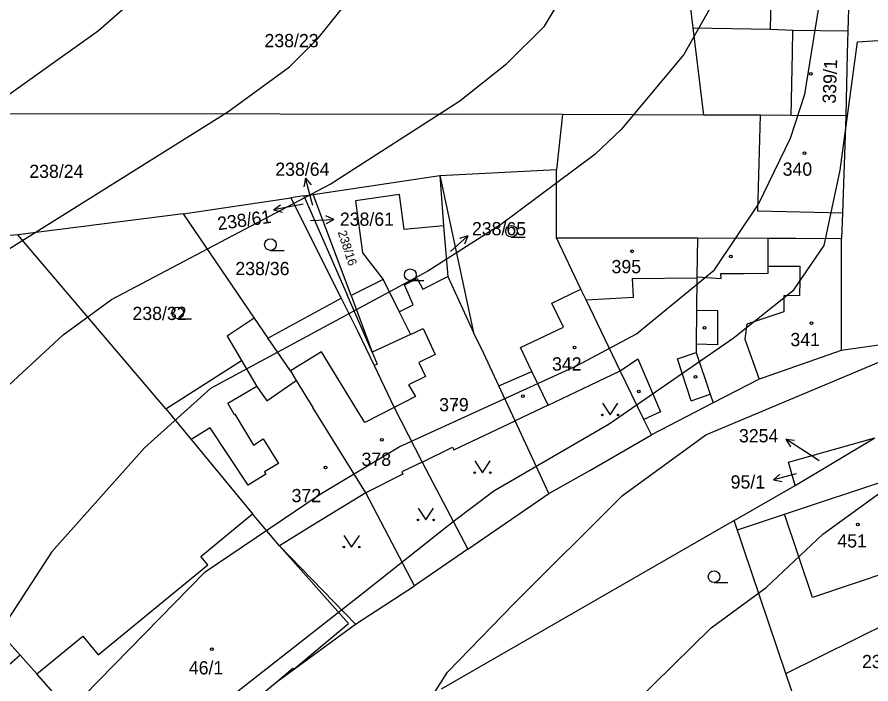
# Model space of a CAD drawing. Extents: x -555860 to -552701, y -1187050 to -1182291.
# Drawn here: x -554606.3 to -554496.6, y -1184422.8 to -1184337.1 of the extents above; entities that cross this region are included whole.
import ezdxf

# ---------------------------------------------------------------- set-up
doc = ezdxf.new("R2010")
doc.units = 0
for name, color, linetype in [('CYKLISTI_stav', 7, 'Continuous'), ('LEG_2b', 7, 'Continuous'), ('Level 16', 7, 'Continuous'), ('Level 25', 7, 'Continuous'), ('Level 40', 7, 'Continuous'), ('Level 41', 7, 'Continuous'), ('navrh_BV', 7, 'Continuous'), ('Poz předměty', 7, 'Continuous'), ('stav_BV', 7, 'Continuous')]:
    doc.layers.add(name, color=color, linetype=linetype)

msp = doc.modelspace()

# ---------------------------------------------------------------- linework, layer by layer
at = {"layer": 'CYKLISTI_stav'}
for p, q in [((-554509.47, -1184338.72), (-554509.23, -1184325.48)), ((-554506.67, -1184341.74), (-554506.62, -1184338.84)), ((-554506.81, -1184349.79), (-554506.67, -1184341.74)), ((-554511.12, -1184362.08), (-554510.76, -1184349.77)), ((-554500.2, -1184362.32), (-554511.12, -1184362.08)), ((-554509.77, -1184369.16), (-554509.77, -1184365.53)), ((-554509.77, -1184369.16), (-554505.69, -1184369.14)), ((-554509.77, -1184370.06), (-554509.77, -1184369.16)), ((-554505.69, -1184369.14), (-554505.69, -1184370.04)), ((-554559.25, -1184370.87), (-554557.18, -1184375.01)), ((-554527.21, -1184370.71), (-554518.94, -1184370.66)), ((-554527.08, -1184373.14), (-554527.21, -1184370.71)), ((-554518.94, -1184370.51), (-554515.83, -1184370.75)), ((-554515.84, -1184370.08), (-554512.85, -1184370.07)), ((-554515.83, -1184370.75), (-554515.84, -1184370.08)), ((-554512.85, -1184370.07), (-554509.77, -1184370.06)), ((-554505.69, -1184371.04), (-554505.76, -1184372.93)), ((-554505.69, -1184370.04), (-554505.69, -1184371.04)), ((-554537.59, -1184373.9), (-554533.83, -1184372.08)), ((-554533.16, -1184373.47), (-554527.08, -1184373.14)), ((-554507.75, -1184372.96), (-554507.76, -1184375.02)), ((-554505.76, -1184372.93), (-554507.75, -1184372.96)), ((-554536.09, -1184376.98), (-554537.59, -1184373.9)), ((-554557.18, -1184375.01), (-554555.72, -1184377.92)), ((-554518.98, -1184374.78), (-554516.29, -1184374.85)), ((-554516.29, -1184374.85), (-554516.3, -1184379.25)), ((-554507.76, -1184375.02), (-554512.5, -1184376.58)), ((-554512.5, -1184376.58), (-554512.77, -1184378.52)), ((-554555.72, -1184377.92), (-554554.09, -1184377.17)), ((-554554.09, -1184377.17), (-554552.57, -1184380.5)), ((-554541.58, -1184379.61), (-554536.09, -1184376.98)), ((-554555.72, -1184377.92), (-554560.66, -1184380.21)), ((-554512.77, -1184378.52), (-554510.93, -1184383.67)), ((-554540.12, -1184382.67), (-554541.58, -1184379.61)), ((-554516.3, -1184379.25), (-554519.02, -1184379.16)), ((-554567.17, -1184380.15), (-554571.16, -1184382.61)), ((-554562.22, -1184388.18), (-554567.17, -1184380.15)), ((-554552.57, -1184380.5), (-554554.65, -1184381.52)), ((-554521.44, -1184381.05), (-554519.03, -1184380.25)), ((-554577.44, -1184381.25), (-554575.45, -1184384.62)), ((-554554.65, -1184381.52), (-554553.8, -1184383.31)), ((-554528.8, -1184382.58), (-554526.51, -1184381.03)), ((-554526.51, -1184381.03), (-554523.62, -1184387.84)), ((-554519.65, -1184386.45), (-554521.44, -1184381.05)), ((-554544.38, -1184384.53), (-554540.12, -1184382.67)), ((-554538.05, -1184386.99), (-554540.12, -1184382.67)), ((-554574.17, -1184386.45), (-554570.42, -1184383.81)), ((-554553.8, -1184383.31), (-554556, -1184384.37)), ((-554575.45, -1184384.62), (-554579.19, -1184386.77)), ((-554575.45, -1184384.62), (-554574.17, -1184386.45)), ((-554556, -1184384.37), (-554555.07, -1184385.9)), ((-554555.07, -1184385.9), (-554557.83, -1184387.32)), ((-554519.65, -1184386.45), (-554517.22, -1184385.6)), ((-554579.19, -1184386.77), (-554578.37, -1184388.2)), ((-554557.83, -1184387.32), (-554561.58, -1184389.22)), ((-554538.05, -1184386.99), (-554542.3, -1184389)), ((-554578.37, -1184388.2), (-554578.28, -1184388.15)), ((-554578.28, -1184388.15), (-554575.91, -1184392.13)), ((-554561.58, -1184389.22), (-554562.22, -1184388.18)), ((-554523.62, -1184387.84), (-554525.73, -1184388.82)), ((-554581.45, -1184389.92), (-554583.89, -1184391.42)), ((-554576.56, -1184397.29), (-554581.45, -1184389.92)), ((-554575.91, -1184392.13), (-554574.67, -1184391.34)), ((-554574.67, -1184391.34), (-554572.69, -1184394.48)), ((-554572.69, -1184394.48), (-554574.48, -1184395.58)), ((-554554.23, -1184394.3), (-554556.84, -1184395.56)), ((-554574.3, -1184395.88), (-554576.56, -1184397.29)), ((-554574.48, -1184395.58), (-554574.3, -1184395.88)), ((-554556.69, -1184395.88), (-554561.48, -1184398.25)), ((-554556.84, -1184395.56), (-554556.69, -1184395.88)), ((-554507.68, -1184401.01), (-554492.26, -1184395.86)), ((-554561.48, -1184398.25), (-554568.25, -1184402.42)), ((-554504.1, -1184411.72), (-554507.68, -1184401.01)), ((-554568.25, -1184402.42), (-554572.55, -1184405.06)), ((-554563.7, -1184415.03), (-554572.55, -1184405.06)), ((-554488.71, -1184406.52), (-554504.1, -1184411.72)), ((-554570.73, -1184420.91), (-554563.7, -1184415.03)), ((-554605.87, -1184419.11), (-554608.01, -1184420.99)), ((-554572.85, -1184422.48), (-554570.82, -1184420.8)), ((-554570.82, -1184420.8), (-554570.73, -1184420.91))]:
    msp.add_line(p, q, dxfattribs=at)
for points in [[(-554557.18, -1184375.01), (-554555.38, -1184374.13), (-554556.5, -1184371.56), (-554554.88, -1184370.71), (-554554.14, -1184372.1), (-554550.93, -1184370.47)], [(-554538.05, -1184386.99), (-554532.63, -1184384.42), (-554528.8, -1184382.58)], [(-554554.23, -1184394.3), (-554550.31, -1184392.41), (-554550.16, -1184392.73), (-554542.3, -1184389)]]:
    msp.add_lwpolyline(points, dxfattribs=at)
at = {"layer": 'Level 16'}
for p, q in [((-554568.57, -1184363.3), (-554565.57, -1184363.15)), ((-554565.57, -1184363.15), (-554566.6, -1184362.7)), ((-554565.57, -1184363.15), (-554566.55, -1184363.7)), ((-554506.2, -1184395.81), (-554509.09, -1184396.6)), ((-554509.09, -1184396.6), (-554508.26, -1184395.86)), ((-554509.09, -1184396.6), (-554508, -1184396.82))]:
    msp.add_line(p, q, dxfattribs=at)
at = {"layer": 'Level 25'}
for p, q in [((-554542.76, -1184365.41), (-554541.01, -1184365.41)), ((-554573.72, -1184367.12), (-554571.97, -1184367.12)), ((-554555.75, -1184371), (-554554, -1184371)), ((-554585.62, -1184375.89), (-554583.87, -1184375.89)), ((-554516.73, -1184409.78), (-554514.98, -1184409.78))]:
    msp.add_line(p, q, dxfattribs=at)
for points in [[(-554531.07, -1184386.75), (-554530.07, -1184388.25), (-554529.07, -1184386.75)], [(-554547.47, -1184394.17), (-554546.47, -1184395.67), (-554545.47, -1184394.17)], [(-554554.75, -1184400.24), (-554553.75, -1184401.74), (-554552.75, -1184400.24)], [(-554564.29, -1184403.73), (-554563.29, -1184405.23), (-554562.29, -1184403.73)]]:
    msp.add_lwpolyline(points, dxfattribs=at)
for centre, radius in [((-554504.3, -1184344.45), 0.175), ((-554505.12, -1184354.64), 0.175), ((-554542.76, -1184364.66), 0.75), ((-554573.72, -1184366.37), 0.75), ((-554527.27, -1184367.24), 0.175), ((-554514.56, -1184367.91), 0.175), ((-554555.75, -1184370.25), 0.75), ((-554585.62, -1184375.14), 0.75), ((-554504.22, -1184376.47), 0.175), ((-554517.95, -1184377.05), 0.175), ((-554534.64, -1184379.6), 0.175), ((-554519.11, -1184383.36), 0.175), ((-554526.41, -1184385.24), 0.175), ((-554541.31, -1184385.84), 0.175), ((-554549.94, -1184386.96), 0.175), ((-554531.07, -1184388.25), 0.1), ((-554529.07, -1184388.25), 0.1), ((-554559.41, -1184391.46), 0.175), ((-554566.63, -1184395), 0.175), ((-554547.47, -1184395.67), 0.1), ((-554545.47, -1184395.67), 0.1), ((-554554.75, -1184401.74), 0.1), ((-554552.75, -1184401.74), 0.1), ((-554498.27, -1184402.34), 0.175), ((-554564.29, -1184405.23), 0.1), ((-554562.29, -1184405.23), 0.1), ((-554516.73, -1184409.03), 0.75), ((-554581.26, -1184418.35), 0.175)]:
    msp.add_circle(centre, radius, dxfattribs=at)
at = {"layer": 'Level 40'}
for points in [[(-554704.42, -1184410.9), (-554700.28, -1184411.43), (-554695.1, -1184411.42), (-554689.74, -1184411.01), (-554685.2, -1184410.27), (-554679.21, -1184408.38), (-554674.31, -1184406.3), (-554667.57, -1184402.23), (-554665.06, -1184399.12), (-554660.22, -1184394.29), (-554648.17, -1184387.43), (-554614.17, -1184371.18), (-554579.17, -1184349.31), (-554571.27, -1184343.52), (-554567.6, -1184339.86), (-554560.69, -1184331.25), (-554554.62, -1184321.09), (-554552.64, -1184316.01), (-554550.39, -1184305.85), (-554550.24, -1184300.77), (-554547.56, -1184285.53), (-554544.03, -1184275.37), (-554531.47, -1184246.3), (-554522.1, -1184219.47)], [(-554655.52, -1184508.62), (-554655.75, -1184500.69), (-554643.25, -1184493.97), (-554633.4, -1184486.78), (-554624.37, -1184479.93), (-554609.65, -1184462.12), (-554602.45, -1184466.42), (-554590.47, -1184463.78), (-554582.07, -1184460.56), (-554576.65, -1184457.21), (-554571.61, -1184452.75), (-554564.45, -1184442.43), (-554550.96, -1184421.3), (-554542.47, -1184412.5), (-554528.47, -1184398.59), (-554517.79, -1184390.83), (-554489.12, -1184378.8)]]:
    msp.add_lwpolyline(points, dxfattribs=at)
at = {"layer": 'Level 41'}
for points in [[(-554723.68, -1184371.89), (-554709.28, -1184375.13), (-554697.99, -1184376.55), (-554685.57, -1184375.98), (-554667.51, -1184373.72), (-554656.22, -1184371.32), (-554643.8, -1184367.23), (-554617.56, -1184353.69), (-554611.07, -1184349.73), (-554595.82, -1184338.87), (-554588.63, -1184332.52), (-554580.72, -1184323.77), (-554575.79, -1184315.73), (-554571.27, -1184305.85), (-554562.8, -1184278.47), (-554556.88, -1184263.94), (-554548.41, -1184246.86), (-554538.48, -1184222.06), (-554535, -1184209.25), (-554534.86, -1184191.85)], [(-554608.54, -1184385.49), (-554600.34, -1184377.96), (-554594.13, -1184373.44), (-554566.05, -1184358.62), (-554549.4, -1184347.9), (-554543.33, -1184343.1), (-554538.53, -1184338.3), (-554532.89, -1184328.99), (-554529.5, -1184318.55), (-554525.12, -1184288.35), (-554517.79, -1184265.77), (-554511.3, -1184251.94), (-554507.68, -1184243.65), (-554506.19, -1184238.79), (-554506.15, -1184230.44)], [(-554686.19, -1184509.5), (-554686.19, -1184504.67), (-554682.39, -1184501.42), (-554679.34, -1184497.68), (-554671.2, -1184491.48), (-554663.95, -1184488.11), (-554651.86, -1184482.13), (-554641.77, -1184475.91), (-554629.84, -1184466.75), (-554621.25, -1184458.3), (-554614.31, -1184450.12), (-554605.02, -1184434.45), (-554597.68, -1184424.32), (-554582.08, -1184408.39), (-554567.32, -1184398.42), (-554557.16, -1184392.35), (-554534.3, -1184381.91), (-554526.68, -1184377.82), (-554516.66, -1184369.63), (-554511.01, -1184361.16), (-554506.92, -1184352.7), (-554505.09, -1184347.05), (-554501.42, -1184324.48)], [(-554517.08, -1184335.76), (-554520.61, -1184341.97), (-554528.65, -1184351.57), (-554532.04, -1184354.81), (-554544.18, -1184363.84), (-554553.49, -1184369.77), (-554581.43, -1184384.87), (-554589.9, -1184392.49), (-554601.83, -1184405.89), (-554634, -1184455.39), (-554637.75, -1184460.66), (-554648.01, -1184471.89), (-554655.91, -1184478.12), (-554666.73, -1184484.09), (-554676.43, -1184487.97), (-554699.73, -1184495.18), (-554705.98, -1184496.32), (-554715.26, -1184497.4)], [(-554671.82, -1184510.68), (-554672.23, -1184504.37), (-554670.15, -1184502.15), (-554645.4, -1184485.96), (-554640.9, -1184483.53), (-554634.7, -1184478.1), (-554627.63, -1184472.97), (-554606.29, -1184450.17), (-554583.21, -1184427.88), (-554562.04, -1184411.29), (-554550.24, -1184401.95), (-554545.02, -1184398), (-554530.2, -1184389.39), (-554514.26, -1184378.38), (-554506.5, -1184372.17), (-554502.57, -1184366.47), (-554500.55, -1184356.83), (-554498.31, -1184340.33), (-554484.62, -1184339.43)], [(-554620.28, -1184511.96), (-554615.57, -1184502.26), (-554615.31, -1184496.89), (-554613.9, -1184495.46), (-554592.41, -1184483.26), (-554577.99, -1184473.69), (-554567.03, -1184464.4), (-554549.15, -1184447.07), (-554517.11, -1184415.59), (-554510.03, -1184410.42), (-554502.76, -1184403.59), (-554494.07, -1184397.28)]]:
    msp.add_lwpolyline(points, dxfattribs=at)
at = {"layer": 'navrh_BV'}
for p, q in [((-554521.09, -1184325.46), (-554519.44, -1184338.52)), ((-554499.5, -1184338.91), (-554499.16, -1184325.57)), ((-554519.44, -1184338.52), (-554509.47, -1184338.72)), ((-554519.44, -1184338.52), (-554518.08, -1184349.75)), ((-554509.47, -1184338.72), (-554506.62, -1184338.84)), ((-554506.62, -1184338.84), (-554499.5, -1184338.91)), ((-554499.57, -1184341.83), (-554499.5, -1184338.91)), ((-554499.78, -1184349.82), (-554499.57, -1184341.83)), ((-554536.2, -1184349.68), (-554626.42, -1184349.54)), ((-554536.2, -1184349.68), (-554536.96, -1184356.72)), ((-554518.08, -1184349.75), (-554536.2, -1184349.68)), ((-554510.76, -1184349.77), (-554518.08, -1184349.75)), ((-554506.81, -1184349.79), (-554510.76, -1184349.77)), ((-554499.78, -1184349.82), (-554506.81, -1184349.79)), ((-554500.2, -1184362.32), (-554499.78, -1184349.82)), ((-554551.95, -1184357.5), (-554536.96, -1184356.72)), ((-554536.96, -1184365.51), (-554536.96, -1184356.72)), ((-554568.24, -1184359.94), (-554551.95, -1184357.5)), ((-554551.95, -1184357.5), (-554551.47, -1184363.96)), ((-554551.95, -1184357.5), (-554547.65, -1184377.67)), ((-554569.41, -1184360.11), (-554571.1, -1184360.36)), ((-554569.41, -1184360.11), (-554568.24, -1184359.94)), ((-554569.41, -1184360.11), (-554563.88, -1184372.82)), ((-554563.34, -1184372.93), (-554568.24, -1184359.94)), ((-554557.14, -1184359.95), (-554562.78, -1184360.75)), ((-554556.54, -1184364.45), (-554557.14, -1184359.95)), ((-554584.94, -1184362.42), (-554571.1, -1184360.36)), ((-554571.1, -1184360.36), (-554564.64, -1184373.24)), ((-554562.78, -1184360.75), (-554561.88, -1184367.43)), ((-554500.31, -1184365.58), (-554500.2, -1184362.32)), ((-554584.94, -1184362.42), (-554606.16, -1184365.14)), ((-554584.94, -1184362.42), (-554575.8, -1184375.81)), ((-554551.47, -1184363.96), (-554556.54, -1184364.45)), ((-554551.47, -1184363.96), (-554550.93, -1184370.47)), ((-554606.16, -1184365.14), (-554628.5, -1184366.61)), ((-554587.15, -1184387.48), (-554606.16, -1184365.14)), ((-554536.96, -1184365.51), (-554519.06, -1184365.49)), ((-554533.83, -1184372.08), (-554536.96, -1184365.51)), ((-554519.06, -1184365.49), (-554518.86, -1184365.49)), ((-554518.86, -1184365.49), (-554518.94, -1184370.51)), ((-554518.86, -1184365.49), (-554509.77, -1184365.53)), ((-554509.77, -1184365.53), (-554506.23, -1184365.55)), ((-554506.23, -1184365.55), (-554500.41, -1184365.58)), ((-554500.41, -1184365.58), (-554500.4, -1184379.99)), ((-554500.41, -1184365.58), (-554500.31, -1184365.58)), ((-554561.88, -1184367.43), (-554559.25, -1184370.87)), ((-554559.25, -1184370.87), (-554563.34, -1184372.93)), ((-554550.93, -1184370.47), (-554547.65, -1184377.67)), ((-554518.94, -1184370.66), (-554518.98, -1184374.78)), ((-554518.94, -1184370.51), (-554518.94, -1184370.66)), ((-554533.16, -1184373.47), (-554533.83, -1184372.08)), ((-554574.03, -1184378.4), (-554564.64, -1184373.24)), ((-554564.64, -1184373.24), (-554562.54, -1184377.44)), ((-554560.66, -1184380.21), (-554563.88, -1184372.82)), ((-554563.34, -1184372.93), (-554560.66, -1184380.21)), ((-554528.8, -1184382.58), (-554533.16, -1184373.47)), ((-554518.98, -1184374.78), (-554519.02, -1184379.16)), ((-554575.8, -1184375.81), (-554579.26, -1184378.15)), ((-554575.8, -1184375.81), (-554574.03, -1184378.4)), ((-554562.54, -1184377.44), (-554560.41, -1184381.91)), ((-554546.32, -1184380.36), (-554547.65, -1184377.67)), ((-554579.26, -1184378.15), (-554577.44, -1184381.25)), ((-554573.72, -1184378.86), (-554574.03, -1184378.4)), ((-554488.55, -1184378.33), (-554500.4, -1184379.99)), ((-554571.16, -1184382.61), (-554573.72, -1184378.86)), ((-554519.02, -1184379.16), (-554519.03, -1184380.25)), ((-554560.66, -1184380.21), (-554560.01, -1184381.72)), ((-554544.38, -1184384.53), (-554546.32, -1184380.36)), ((-554519.03, -1184380.25), (-554517.22, -1184385.6)), ((-554501.25, -1184380.29), (-554510.4, -1184383.49)), ((-554500.4, -1184379.99), (-554501.25, -1184380.29)), ((-554587.15, -1184387.48), (-554577.44, -1184381.25)), ((-554560.01, -1184381.72), (-554560.41, -1184381.91)), ((-554560.41, -1184381.91), (-554557.83, -1184387.32)), ((-554571.16, -1184382.61), (-554570.42, -1184383.81)), ((-554525.73, -1184388.82), (-554528.8, -1184382.58)), ((-554570.42, -1184383.81), (-554568.27, -1184387.29)), ((-554510.93, -1184383.67), (-554516.84, -1184386.71)), ((-554510.4, -1184383.49), (-554510.93, -1184383.67)), ((-554542.3, -1184389), (-554544.38, -1184384.53)), ((-554517.22, -1184385.6), (-554516.84, -1184386.71)), ((-554587.15, -1184387.48), (-554583.89, -1184391.42)), ((-554561.48, -1184398.25), (-554568.27, -1184387.29)), ((-554557.83, -1184387.32), (-554554.23, -1184394.3)), ((-554516.84, -1184386.71), (-554524.77, -1184390.79)), ((-554537.96, -1184398.36), (-554542.3, -1184389)), ((-554524.77, -1184390.79), (-554525.73, -1184388.82)), ((-554532.69, -1184395.37), (-554524.77, -1184390.79)), ((-554583.89, -1184391.42), (-554576.01, -1184400.95)), ((-554507.15, -1184394.31), (-554496.06, -1184391.2)), ((-554506.29, -1184397.32), (-554496.06, -1184391.2)), ((-554554.23, -1184394.3), (-554548.38, -1184405.51)), ((-554506.29, -1184397.32), (-554507.15, -1184394.31)), ((-554537.96, -1184398.36), (-554532.69, -1184395.37)), ((-554514.13, -1184401.83), (-554506.29, -1184397.32)), ((-554555.22, -1184410.2), (-554561.48, -1184398.25)), ((-554548.38, -1184405.51), (-554537.96, -1184398.36)), ((-554582.64, -1184406.45), (-554576.01, -1184400.95)), ((-554572.55, -1184405.06), (-554576.01, -1184400.95)), ((-554514.13, -1184401.83), (-554551.78, -1184423.5)), ((-554507.5, -1184421.48), (-554514.13, -1184401.83)), ((-554562.77, -1184415.14), (-554572.55, -1184405.06)), ((-554548.38, -1184405.51), (-554555.22, -1184410.2)), ((-554581.77, -1184407.5), (-554582.64, -1184406.45)), ((-554595.83, -1184419.07), (-554581.77, -1184407.5)), ((-554507.5, -1184421.48), (-554479.36, -1184407.47)), ((-554562.77, -1184415.14), (-554555.22, -1184410.2)), ((-554568.86, -1184419.58), (-554562.77, -1184415.14)), ((-554603.74, -1184421.52), (-554597.82, -1184416.65)), ((-554597.82, -1184416.65), (-554595.83, -1184419.07)), ((-554605.87, -1184419.11), (-554607.23, -1184417.56)), ((-554603.74, -1184421.52), (-554605.87, -1184419.11)), ((-554572.85, -1184422.48), (-554568.86, -1184419.58)), ((-554601.67, -1184423.87), (-554603.74, -1184421.52)), ((-554504.94, -1184429.06), (-554507.5, -1184421.48)), ((-554590.45, -1184437.03), (-554572.85, -1184422.48))]:
    msp.add_line(p, q, dxfattribs=at)
at = {"layer": 'Poz předměty'}
msp.add_lwpolyline([(-554513.72, -1184403.03), (-554507.68, -1184401.01)], dxfattribs=at)
at = {"layer": 'stav_BV'}
for p, q in [((-554569.22, -1184357.85), (-554569.44, -1184358.95)), ((-554568.44, -1184360.75), (-554569.22, -1184357.85)), ((-554569.22, -1184357.85), (-554568.47, -1184358.69)), ((-554573.31, -1184361.93), (-554572.42, -1184361.25)), ((-554569.51, -1184361.2), (-554570.36, -1184361.36)), ((-554568.29, -1184361.34), (-554568.44, -1184360.75)), ((-554570.36, -1184361.36), (-554573.31, -1184361.93)), ((-554573.31, -1184361.93), (-554572.23, -1184362.23)), ((-554550.6, -1184367.28), (-554548.37, -1184365.27)), ((-554548.37, -1184365.27), (-554549.45, -1184365.57)), ((-554548.37, -1184365.27), (-554548.78, -1184366.31)), ((-554504.98, -1184393), (-554507.5, -1184391.37)), ((-554507.5, -1184391.37), (-554506.38, -1184391.49)), ((-554507.5, -1184391.37), (-554506.93, -1184392.33)), ((-554503.24, -1184394.15), (-554504.98, -1184393))]:
    msp.add_line(p, q, dxfattribs=at)

# ---------------------------------------------------------------- texts
at = {"layer": 'LEG_2b'}
for s, p in [('238/23', (-554574.48, -1184341.02)), ('238/64', (-554573.09, -1184357.54)), ('238/24', (-554604.69, -1184357.81)), ('340', (-554507.92, -1184357.53)), ('238/65', (-554547.83, -1184365.18)), ('238/36', (-554578.22, -1184370.3)), ('395', (-554529.9, -1184370.05)), ('238/32', (-554591.44, -1184376.06)), ('341', (-554506.92, -1184379.42)), ('342', (-554537.54, -1184382.55)), ('379', (-554552.04, -1184387.78)), ('3254', (-554513.53, -1184391.78)), ('378', (-554562.01, -1184394.8)), ('372', (-554571, -1184399.46)), ('451', (-554500.89, -1184405.28)), ('231/3', (-554497.72, -1184420.78)), ('46/1', (-554584.2, -1184421.58))]:
    msp.add_text(s, height=1.7, dxfattribs=at).set_placement(p)
for s, height, rotation, p in [('339/1', 1.7, 88, (-554501.1, -1184348.29)), ('238/61', 1.7, 8, (-554580.41, -1184364.54)), ('238/16', 1.139, 288, (-554565.08, -1184364.77))]:
    msp.add_text(s, height=height, rotation=rotation, dxfattribs=at).set_placement(p)
at = {"layer": 'Level 16'}
for s, p in [('238/61', (-554564.8, -1184363.96)), ('95/1', (-554514.6, -1184397.71))]:
    msp.add_text(s, height=1.7, dxfattribs=at).set_placement(p)

doc.saveas('drawing.dxf')
